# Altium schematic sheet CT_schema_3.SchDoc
size 405 x 321 mm
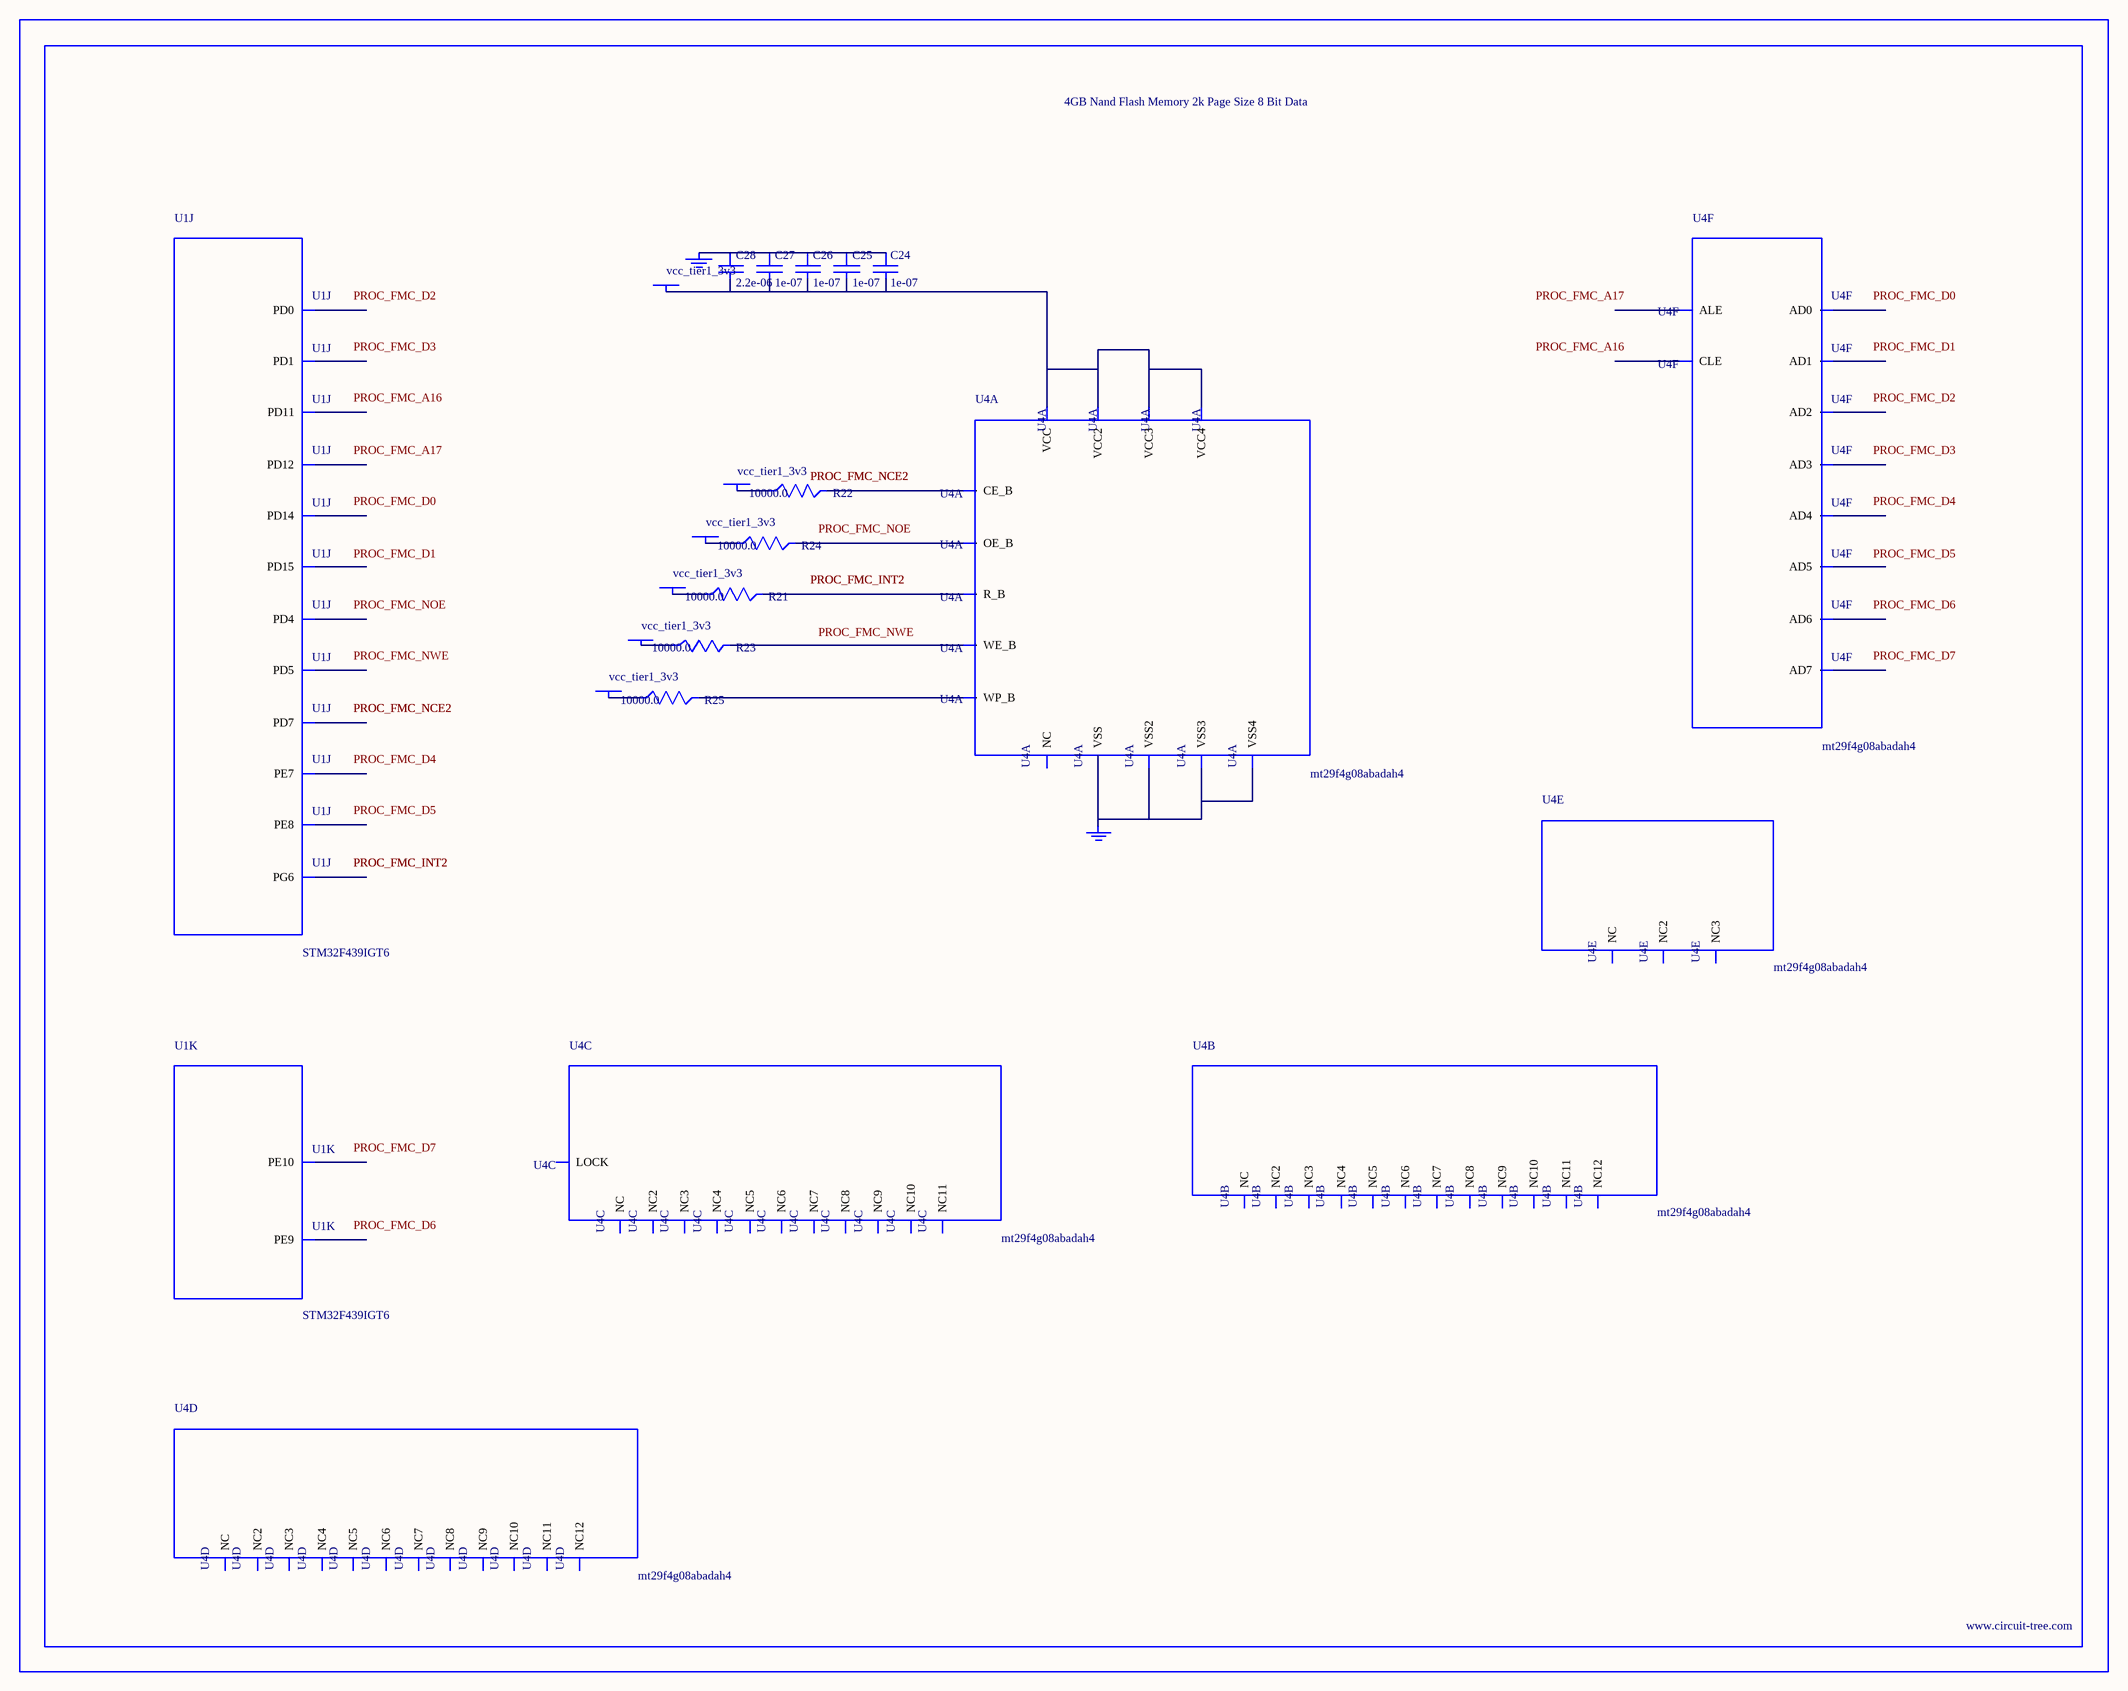
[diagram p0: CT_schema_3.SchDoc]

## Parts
BORDER2  (no value)
C24  1e-07  [C0402]
C25  1e-07  [C0402]
C26  1e-07  [C0402]
C27  1e-07  [C0402]
C28  2.2e-06  [C0603]
GND_INSTANCE_2_0  (no value)
GND_INSTANCE_2_1  (no value)
POWER_INSTANCE_2_0  vcc_tier1_3v3
POWER_INSTANCE_2_1  vcc_tier1_3v3
POWER_INSTANCE_2_2  vcc_tier1_3v3
POWER_INSTANCE_2_3  vcc_tier1_3v3
POWER_INSTANCE_2_4  vcc_tier1_3v3
POWER_INSTANCE_2_5  vcc_tier1_3v3
R21  10000.0  [R0603]
R22  10000.0  [R0603]
R23  10000.0  [R0603]
R24  10000.0  [R0603]
R25  10000.0  [R0603]
U1  STM32F439IGT6  [LQFP176]  (parts J,K of 14)
U4  mt29f4g08abadah4  [VFBGA-63]  (parts A,B,C,D,E,F of 6)

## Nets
NetC24_1: C24.1 C25.1 C26.1 C27.1 C28.1 GND_INSTANCE_2_0.0(GND)
NetC24_2: C24.2 C25.2 C26.2 C27.2 C28.2 POWER_INSTANCE_2_0.0(PWR) U4.D3(VCC) U4.G4(VCC2) U4.H8(VCC3) U4.J6(VCC4)
NetGND_INSTANCE_2_1_0: GND_INSTANCE_2_1.0(GND) U4.C5(VSS) U4.F7(VSS2) U4.K3(VSS3) U4.K8(VSS4)
NetPOWER_INSTANCE_2_1_0: POWER_INSTANCE_2_1.0(PWR) R21.1
NetPOWER_INSTANCE_2_2_0: POWER_INSTANCE_2_2.0(PWR) R22.1
NetPOWER_INSTANCE_2_3_0: POWER_INSTANCE_2_3.0(PWR) R23.1
NetPOWER_INSTANCE_2_4_0: POWER_INSTANCE_2_4.0(PWR) R24.1
NetPOWER_INSTANCE_2_5_0: POWER_INSTANCE_2_5.0(PWR) R25.1
NetR21_2: R21.2 U4.C8(R_B)
NetR22_2: R22.2 U4.C6(CE_B)
NetR23_2: R23.2 U4.C7(WE_B)
NetR24_2: R24.2 U4.D4(OE_B)
NetR25_2: R25.2 U4.C3(WP_B)

Not connected (* = marked no-connect by the designer): U1 68(PE7) 69(PE8) 70(PE9) 73(PE10) 99(PD11) 100(PD12) 104(PD14) 105(PD15) 110(PG6) 142(PD0) 143(PD1) 146(PD4) 147(PD5) 151(PD7); U4 A1(NC) A2(NC3) A9(NC4) A10(NC2) B1(NC5) B9(NC7) B10(NC6) C4(ALE) D5(CLE) D6(NC8) D7(NC9) D8(NC10) E3(NC11) E4(NC12) E5(NC) E6(NC2) E7(NC3) E8(NC4) F3(NC5) F4(NC6) F5(NC7) F6(NC8) F8(NC9) G3(NC) G5(LOCK) G6(NC10) G7(NC11) G8(NC) H3(NC2) H4(AD0) H5(NC3) H6(NC4) H7(NC5) J3(NC6) J4(AD1) J5(NC7) J7(AD5) J8(AD7) K4(AD2) K5(AD3) K6(AD4) K7(AD6) L1(NC8) L2(NC10) L9(NC11) L10(NC9) M1(NC12) M2(NC2) M9(NC3) M10(NC)

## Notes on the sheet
- Labels drawn without touching a wire or pin: PROC_FMC_A16, PROC_FMC_A17, PROC_FMC_D0, PROC_FMC_D1, PROC_FMC_D2, PROC_FMC_D3, PROC_FMC_D4, PROC_FMC_D5, PROC_FMC_D6, PROC_FMC_D7, PROC_FMC_NOE, PROC_FMC_NWE

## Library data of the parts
BORDER2 = BORDER_PAGE2
C24-C27 = C0402C104K3RACTU
C28 = C0603C225K8RACTU
GND_INSTANCE_2_0 GND_INSTANCE_2_1 = GND
POWER_INSTANCE_2_0-POWER_INSTANCE_2_5 = PWR
R21-R25 = RC0603JR-0710KL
